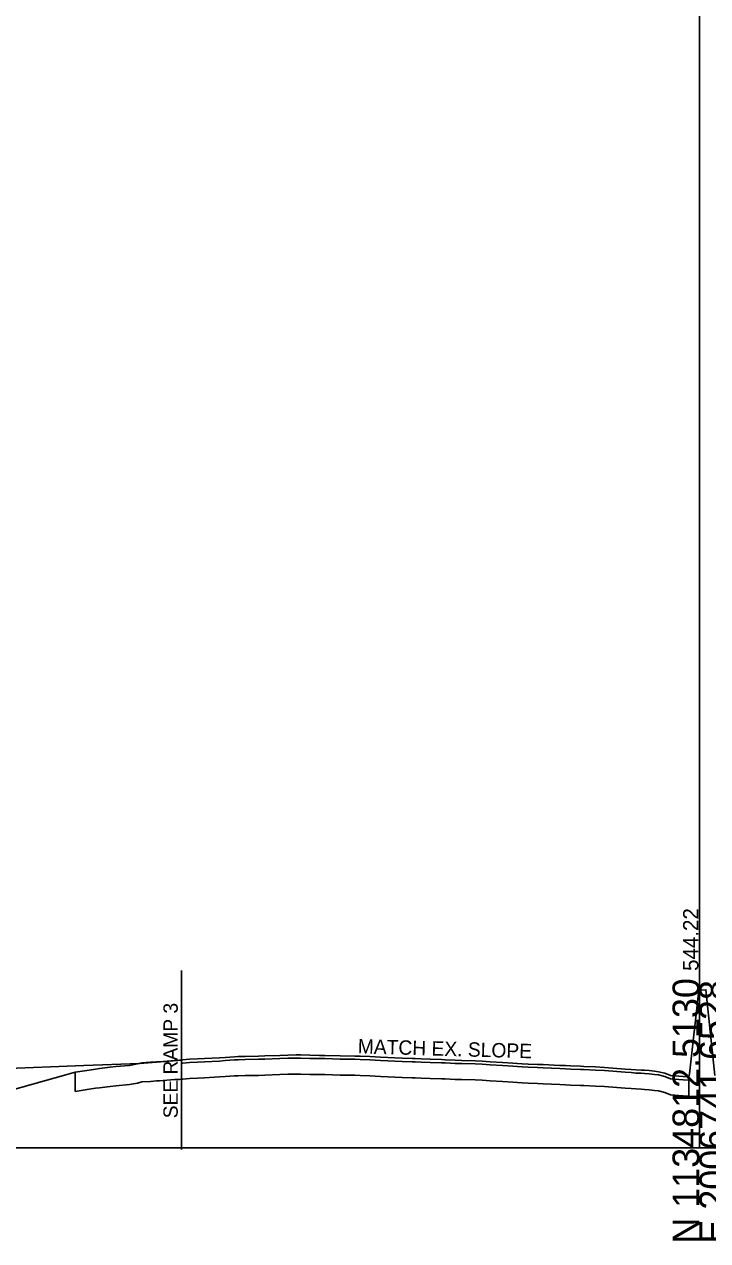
# Model space of a CAD drawing. Extents: x -201 to 2007062, y -213 to 1139737.
# Drawn here: x 1179.6 to 1250.9, y 1490.3 to 1617.2 of the extents above; entities that cross this region are included whole.
import ezdxf

# ---------------------------------------------------------------- set-up
doc = ezdxf.new("R2010")
doc.units = 0
for name, color, linetype in [('RD_DTM_Design_FG', 7, 'Continuous'), ('RD_GPK_XS_Cell', 7, 'Continuous'), ('RD_XS_ExGround', 7, 'Continuous'), ('RD_XS_ExPaveRet', 7, 'Continuous'), ('RD_XS_PaveOvlay', 7, 'Continuous'), ('RD_XS_SideStreet', 7, 'Continuous'), ('RD_XS_TX_Elev_EX', 7, 'Continuous'), ('RD_XS_TX_Slope', 7, 'Continuous')]:
    doc.layers.add(name, color=color, linetype=linetype)

msp = doc.modelspace()

# ---------------------------------------------------------------- linework, layer by layer
at = {"layer": 'RD_DTM_Design_FG'}
msp.add_lwpolyline([(1071.19, 1577.63), (1093.72, 1555.08), (1147.64, 1501.11), (1164.42, 1506.67), (1165.65, 1507.08), (1169.65, 1507.72), (1175.66, 1508.19), (1177.06, 1508.24), (1185.83, 1508.58), (1191.63, 1508.8), (1191.67, 1508.8), (1196, 1509.14)], dxfattribs=at)
at = {"layer": 'RD_GPK_XS_Cell'}
for p, q in [((1250, 1500), (1250, 1741.21)), ((1000, 1500), (1250, 1500)), ((1250, 1500), (1500, 1500))]:
    msp.add_line(p, q, dxfattribs=at)
at = {"layer": 'RD_XS_ExGround'}
msp.add_lwpolyline([(1170.08, 1503.72), (1183.95, 1507.61), (1184.91, 1507.88), (1186.4, 1508.1), (1187.05, 1508.2), (1187.45, 1508.25), (1188.57, 1508.39), (1189.17, 1508.46), (1190.58, 1508.59), (1191.42, 1508.74), (1191.89, 1508.87), (1192.78, 1508.92), (1193.41, 1508.96), (1193.71, 1508.97), (1195.29, 1509.11), (1195.8, 1509.13), (1196.16, 1509.16), (1196.84, 1509.22), (1197.66, 1509.27), (1198.42, 1509.3), (1199.98, 1509.38), (1200.57, 1509.42), (1201.55, 1509.49), (1201.9, 1509.5), (1202.63, 1509.52), (1204.02, 1509.55), (1204.68, 1509.57), (1206.25, 1509.63), (1207.11, 1509.67), (1207.95, 1509.68), (1208.41, 1509.68), (1209.39, 1509.65), (1210.38, 1509.63), (1210.95, 1509.62), (1212.56, 1509.58), (1214.09, 1509.56), (1214.63, 1509.55), (1215.65, 1509.5), (1216.75, 1509.44), (1219, 1509.33), (1220.05, 1509.29), (1220.36, 1509.29), (1220.99, 1509.26), (1221.92, 1509.22), (1223.11, 1509.19), (1223.49, 1509.18), (1224.55, 1509.13), (1225.23, 1509.11), (1226.62, 1509.07), (1227.36, 1509.03), (1228.19, 1508.96), (1229.48, 1508.89), (1230.55, 1508.83), (1231.54, 1508.76), (1232.16, 1508.73), (1233.11, 1508.69), (1233.72, 1508.67), (1235.46, 1508.59), (1236.03, 1508.57), (1236.55, 1508.54), (1237.59, 1508.49), (1237.96, 1508.48), (1239.16, 1508.43), (1240.09, 1508.38), (1242.26, 1508.2), (1242.87, 1508.16), (1243.36, 1508.13), (1243.92, 1508.1), (1244.29, 1508.08), (1244.77, 1508.04), (1245.33, 1507.98), (1245.72, 1507.92), (1246.39, 1507.77), (1247, 1507.53), (1248.29, 1507.42), (1248.9, 1507.38), (1248.97, 1507.69), (1249.93, 1516.44), (1250.68, 1516.48), (1251.62, 1507.55)], dxfattribs=at)
at = {"layer": 'RD_XS_ExPaveRet'}
for p, q in [((1196, 1508.81), (1196, 1507.14)), ((1184.91, 1505.88), (1184.91, 1507.88)), ((1193.71, 1506.97), (1195.29, 1507.11)), ((1195.29, 1507.11), (1195.8, 1507.13)), ((1195.8, 1507.13), (1196.16, 1507.16)), ((1196, 1507.14), (1196.16, 1507.16)), ((1196.16, 1507.16), (1196.84, 1507.22)), ((1196.16, 1507.16), (1196.84, 1507.22)), ((1196.84, 1507.22), (1197.66, 1507.27)), ((1196.84, 1507.22), (1197.66, 1507.27)), ((1197.66, 1507.27), (1198.42, 1507.3)), ((1197.66, 1507.27), (1198.42, 1507.3)), ((1198.42, 1507.3), (1199.98, 1507.38)), ((1198.42, 1507.3), (1199.98, 1507.38)), ((1199.98, 1507.38), (1200.57, 1507.42)), ((1199.98, 1507.38), (1200.57, 1507.42)), ((1200.57, 1507.42), (1201.55, 1507.49)), ((1200.57, 1507.42), (1201.55, 1507.49)), ((1201.55, 1507.49), (1201.9, 1507.5)), ((1201.55, 1507.49), (1201.9, 1507.5)), ((1201.9, 1507.5), (1202.63, 1507.52)), ((1201.9, 1507.5), (1202.63, 1507.52)), ((1202.63, 1507.52), (1204.02, 1507.55)), ((1202.63, 1507.52), (1204.02, 1507.55)), ((1204.02, 1507.55), (1204.68, 1507.57)), ((1204.02, 1507.55), (1204.68, 1507.57)), ((1204.68, 1507.57), (1206.25, 1507.63)), ((1204.68, 1507.57), (1206.25, 1507.63)), ((1206.25, 1507.63), (1207.11, 1507.67)), ((1206.25, 1507.63), (1207.11, 1507.67)), ((1207.11, 1507.67), (1207.95, 1507.68)), ((1207.11, 1507.67), (1207.95, 1507.68)), ((1207.95, 1507.68), (1208.41, 1507.68)), ((1207.95, 1507.68), (1208.41, 1507.68)), ((1208.41, 1507.68), (1209.39, 1507.65)), ((1208.41, 1507.68), (1209.39, 1507.65)), ((1209.39, 1507.65), (1210.38, 1507.63)), ((1209.39, 1507.65), (1210.38, 1507.63)), ((1210.38, 1507.63), (1210.95, 1507.62)), ((1210.38, 1507.63), (1210.95, 1507.62)), ((1210.95, 1507.62), (1212.56, 1507.58)), ((1210.95, 1507.62), (1212.56, 1507.58)), ((1212.56, 1507.58), (1214.09, 1507.56)), ((1212.56, 1507.58), (1214.09, 1507.56)), ((1214.09, 1507.56), (1214.63, 1507.55)), ((1214.09, 1507.56), (1214.63, 1507.55)), ((1214.63, 1507.55), (1215.65, 1507.5)), ((1214.63, 1507.55), (1215.65, 1507.5)), ((1215.65, 1507.5), (1216.75, 1507.44)), ((1215.65, 1507.5), (1216.75, 1507.44)), ((1216.75, 1507.44), (1219, 1507.33)), ((1216.75, 1507.44), (1219, 1507.33)), ((1219, 1507.33), (1220.05, 1507.29)), ((1219, 1507.33), (1220.05, 1507.29)), ((1220.05, 1507.29), (1220.36, 1507.29)), ((1220.05, 1507.29), (1220.36, 1507.29)), ((1220.36, 1507.29), (1220.99, 1507.26)), ((1220.36, 1507.29), (1220.99, 1507.26)), ((1220.99, 1507.26), (1221.92, 1507.22)), ((1220.99, 1507.26), (1221.92, 1507.22)), ((1221.92, 1507.22), (1223.11, 1507.19)), ((1221.92, 1507.22), (1223.11, 1507.19)), ((1223.11, 1507.19), (1223.49, 1507.18)), ((1223.11, 1507.19), (1223.49, 1507.18)), ((1223.49, 1507.18), (1224.55, 1507.13)), ((1223.49, 1507.18), (1224.55, 1507.13)), ((1224.55, 1507.13), (1225.23, 1507.11)), ((1224.55, 1507.13), (1225.23, 1507.11)), ((1225.23, 1507.11), (1226.62, 1507.07)), ((1225.23, 1507.11), (1226.62, 1507.07)), ((1226.62, 1507.07), (1227.36, 1507.03)), ((1226.62, 1507.07), (1227.36, 1507.03)), ((1227.36, 1507.03), (1228.19, 1506.96)), ((1227.36, 1507.03), (1228.19, 1506.96)), ((1248.9, 1507.38), (1248.9, 1505.38)), ((1248.9, 1505.38), (1248.9, 1507.05)), ((1184.91, 1505.88), (1186.4, 1506.1)), ((1186.4, 1506.1), (1187.05, 1506.2)), ((1187.05, 1506.2), (1187.45, 1506.25)), ((1187.45, 1506.25), (1188.57, 1506.39)), ((1188.57, 1506.39), (1189.17, 1506.46)), ((1189.17, 1506.46), (1190.58, 1506.59)), ((1190.58, 1506.59), (1191.42, 1506.74)), ((1191.42, 1506.74), (1191.89, 1506.87)), ((1191.89, 1506.87), (1192.78, 1506.92)), ((1192.78, 1506.92), (1193.41, 1506.96)), ((1193.41, 1506.96), (1193.71, 1506.97)), ((1228.19, 1506.96), (1229.48, 1506.89)), ((1228.19, 1506.96), (1229.48, 1506.89)), ((1229.48, 1506.89), (1230.55, 1506.83)), ((1229.48, 1506.89), (1230.55, 1506.83)), ((1230.55, 1506.83), (1231.54, 1506.76)), ((1230.55, 1506.83), (1231.54, 1506.76)), ((1231.54, 1506.76), (1232.16, 1506.73)), ((1231.54, 1506.76), (1232.16, 1506.73)), ((1232.16, 1506.73), (1233.11, 1506.69)), ((1232.16, 1506.73), (1233.11, 1506.69)), ((1233.11, 1506.69), (1233.72, 1506.67)), ((1233.11, 1506.69), (1233.72, 1506.67)), ((1233.72, 1506.67), (1235.46, 1506.59)), ((1233.72, 1506.67), (1235.46, 1506.59)), ((1235.46, 1506.59), (1236.03, 1506.57)), ((1235.46, 1506.59), (1236.03, 1506.57)), ((1236.03, 1506.57), (1236.55, 1506.54)), ((1236.03, 1506.57), (1236.55, 1506.54)), ((1236.55, 1506.54), (1237.59, 1506.49)), ((1236.55, 1506.54), (1237.59, 1506.49)), ((1237.59, 1506.49), (1237.96, 1506.48)), ((1237.59, 1506.49), (1237.96, 1506.48)), ((1237.96, 1506.48), (1239.16, 1506.43)), ((1237.96, 1506.48), (1239.16, 1506.43)), ((1239.16, 1506.43), (1240.09, 1506.38)), ((1239.16, 1506.43), (1240.09, 1506.38)), ((1240.09, 1506.38), (1242.26, 1506.2)), ((1240.09, 1506.38), (1242.26, 1506.2)), ((1242.26, 1506.2), (1242.87, 1506.16)), ((1242.26, 1506.2), (1242.87, 1506.16)), ((1242.87, 1506.16), (1243.36, 1506.13)), ((1242.87, 1506.16), (1243.36, 1506.13)), ((1243.36, 1506.13), (1243.92, 1506.1)), ((1243.36, 1506.13), (1243.92, 1506.1)), ((1243.92, 1506.1), (1244.29, 1506.08)), ((1243.92, 1506.1), (1244.29, 1506.08)), ((1244.29, 1506.08), (1244.77, 1506.04)), ((1244.29, 1506.08), (1244.77, 1506.04)), ((1244.77, 1506.04), (1245.33, 1505.98)), ((1244.77, 1506.04), (1245.33, 1505.98)), ((1245.33, 1505.98), (1245.72, 1505.92)), ((1245.33, 1505.98), (1245.72, 1505.92)), ((1245.72, 1505.92), (1246.39, 1505.77)), ((1245.72, 1505.92), (1246.39, 1505.77)), ((1246.39, 1505.77), (1247, 1505.53)), ((1246.39, 1505.77), (1247, 1505.53)), ((1247, 1505.53), (1248.29, 1505.42)), ((1247, 1505.53), (1248.29, 1505.42)), ((1248.29, 1505.42), (1248.9, 1505.38)), ((1248.29, 1505.42), (1248.9, 1505.38))]:
    msp.add_line(p, q, dxfattribs=at)
for points in [[(1248.9, 1507.05), (1248.29, 1507.09), (1247, 1507.2), (1246.39, 1507.44), (1245.72, 1507.59), (1245.33, 1507.64), (1244.77, 1507.71), (1244.29, 1507.75), (1243.92, 1507.77), (1243.36, 1507.79), (1242.87, 1507.83), (1242.26, 1507.87), (1240.09, 1508.05), (1239.16, 1508.1), (1237.96, 1508.15), (1237.59, 1508.16), (1236.55, 1508.21), (1236.03, 1508.23), (1235.46, 1508.26), (1233.72, 1508.33), (1233.11, 1508.35), (1232.16, 1508.4), (1231.54, 1508.43), (1230.55, 1508.5), (1229.48, 1508.56), (1228.19, 1508.63), (1227.36, 1508.7), (1226.62, 1508.74), (1225.23, 1508.78), (1224.55, 1508.8), (1223.49, 1508.84), (1223.11, 1508.86), (1221.92, 1508.89), (1220.99, 1508.93), (1220.36, 1508.95), (1220.05, 1508.96), (1219, 1509), (1216.75, 1509.1), (1215.65, 1509.17), (1214.63, 1509.21), (1214.09, 1509.23), (1212.56, 1509.25), (1210.95, 1509.29), (1210.38, 1509.3), (1209.39, 1509.32), (1208.41, 1509.35), (1207.95, 1509.34), (1207.11, 1509.34), (1206.25, 1509.3), (1204.68, 1509.24), (1204.02, 1509.22), (1202.63, 1509.19), (1201.9, 1509.16), (1201.55, 1509.15), (1200.57, 1509.09), (1199.98, 1509.04), (1198.42, 1508.97), (1197.66, 1508.94), (1196.84, 1508.88), (1196.16, 1508.82), (1196, 1508.81)], [(1248.9, 1507.05), (1248.9, 1507.05)]]:
    msp.add_lwpolyline(points, dxfattribs=at)
at = {"layer": 'RD_XS_PaveOvlay'}
msp.add_line((1196, 1509.14), (1196, 1508.81), dxfattribs=at)
for points in [[(1196, 1509.14), (1196.16, 1509.16), (1196.84, 1509.22), (1197.66, 1509.27), (1198.42, 1509.3), (1199.98, 1509.38), (1200.57, 1509.42), (1201.55, 1509.49), (1201.9, 1509.5), (1202.63, 1509.52), (1204.02, 1509.55), (1204.68, 1509.57), (1206.25, 1509.63), (1207.11, 1509.67), (1207.95, 1509.68), (1208.41, 1509.68), (1209.39, 1509.65), (1210.38, 1509.63), (1210.95, 1509.62), (1212.56, 1509.58), (1214.09, 1509.56), (1214.63, 1509.55), (1215.65, 1509.5), (1216.75, 1509.44), (1219, 1509.33), (1220.05, 1509.29), (1220.36, 1509.29), (1220.99, 1509.26), (1221.92, 1509.22), (1223.11, 1509.19), (1223.49, 1509.18), (1224.55, 1509.13), (1225.23, 1509.11), (1226.62, 1509.07), (1227.36, 1509.03), (1228.19, 1508.96), (1229.48, 1508.89), (1230.55, 1508.83), (1231.54, 1508.76), (1232.16, 1508.73), (1233.11, 1508.69), (1233.72, 1508.67), (1235.46, 1508.59), (1236.03, 1508.57), (1236.55, 1508.54), (1237.59, 1508.49), (1237.96, 1508.48), (1239.16, 1508.43), (1240.09, 1508.38), (1242.26, 1508.2), (1242.87, 1508.16), (1243.36, 1508.13), (1243.92, 1508.1), (1244.29, 1508.08), (1244.77, 1508.04), (1245.33, 1507.98), (1245.72, 1507.92), (1246.39, 1507.77), (1247, 1507.53), (1248.29, 1507.42), (1248.9, 1507.38)], [(1196, 1508.81), (1196.16, 1508.82), (1196.84, 1508.88), (1197.66, 1508.94), (1198.42, 1508.97), (1199.98, 1509.04), (1200.57, 1509.09), (1201.55, 1509.15), (1201.9, 1509.16), (1202.63, 1509.19), (1204.02, 1509.22), (1204.68, 1509.24), (1206.25, 1509.3), (1207.11, 1509.34), (1207.95, 1509.34), (1208.41, 1509.35), (1209.39, 1509.32), (1210.38, 1509.3), (1210.95, 1509.29), (1212.56, 1509.25), (1214.09, 1509.23), (1214.63, 1509.21), (1215.65, 1509.17), (1216.75, 1509.1), (1219, 1509), (1220.05, 1508.96), (1220.36, 1508.95), (1220.99, 1508.93), (1221.92, 1508.89), (1223.11, 1508.86), (1223.49, 1508.84), (1224.55, 1508.8), (1225.23, 1508.78), (1226.62, 1508.74), (1227.36, 1508.7), (1228.19, 1508.63), (1229.48, 1508.56), (1230.55, 1508.5), (1231.54, 1508.43), (1232.16, 1508.4), (1233.11, 1508.35), (1233.72, 1508.33), (1235.46, 1508.26), (1236.03, 1508.23), (1236.55, 1508.21), (1237.59, 1508.16), (1237.96, 1508.15), (1239.16, 1508.1), (1240.09, 1508.05), (1242.26, 1507.87), (1242.87, 1507.83), (1243.36, 1507.79), (1243.92, 1507.77), (1244.29, 1507.75), (1244.77, 1507.71), (1245.33, 1507.64), (1245.72, 1507.59), (1246.39, 1507.44), (1247, 1507.2), (1248.29, 1507.09), (1248.9, 1507.05)]]:
    msp.add_lwpolyline(points, dxfattribs=at)
at = {"layer": 'RD_XS_SideStreet'}
msp.add_line((1196, 1518.48), (1196, 1499.8), dxfattribs=at)

# ---------------------------------------------------------------- texts
at = {"layer": 'RD_GPK_XS_Cell'}
for s, p in [('N 1134812.5130', (1250, 1490)), ('E 2006741.6528', (1252.8, 1490))]:
    msp.add_text(s, height=2.8, rotation=90, dxfattribs=at).set_placement(p)
at = {"layer": 'RD_XS_SideStreet'}
msp.add_text('SEE RAMP 3', height=1.5, rotation=90, dxfattribs=at).set_placement((1195.62, 1503.07))
at = {"layer": 'RD_XS_TX_Elev_EX'}
msp.add_text('544.22', height=1.6, rotation=90, dxfattribs=at).set_placement((1249.9, 1518.44))
at = {"layer": 'RD_XS_TX_Slope'}
msp.add_text('MATCH EX. SLOPE', height=1.5, rotation=358.3671, dxfattribs=at).set_placement((1214.37, 1509.84))

doc.saveas('drawing.dxf')
